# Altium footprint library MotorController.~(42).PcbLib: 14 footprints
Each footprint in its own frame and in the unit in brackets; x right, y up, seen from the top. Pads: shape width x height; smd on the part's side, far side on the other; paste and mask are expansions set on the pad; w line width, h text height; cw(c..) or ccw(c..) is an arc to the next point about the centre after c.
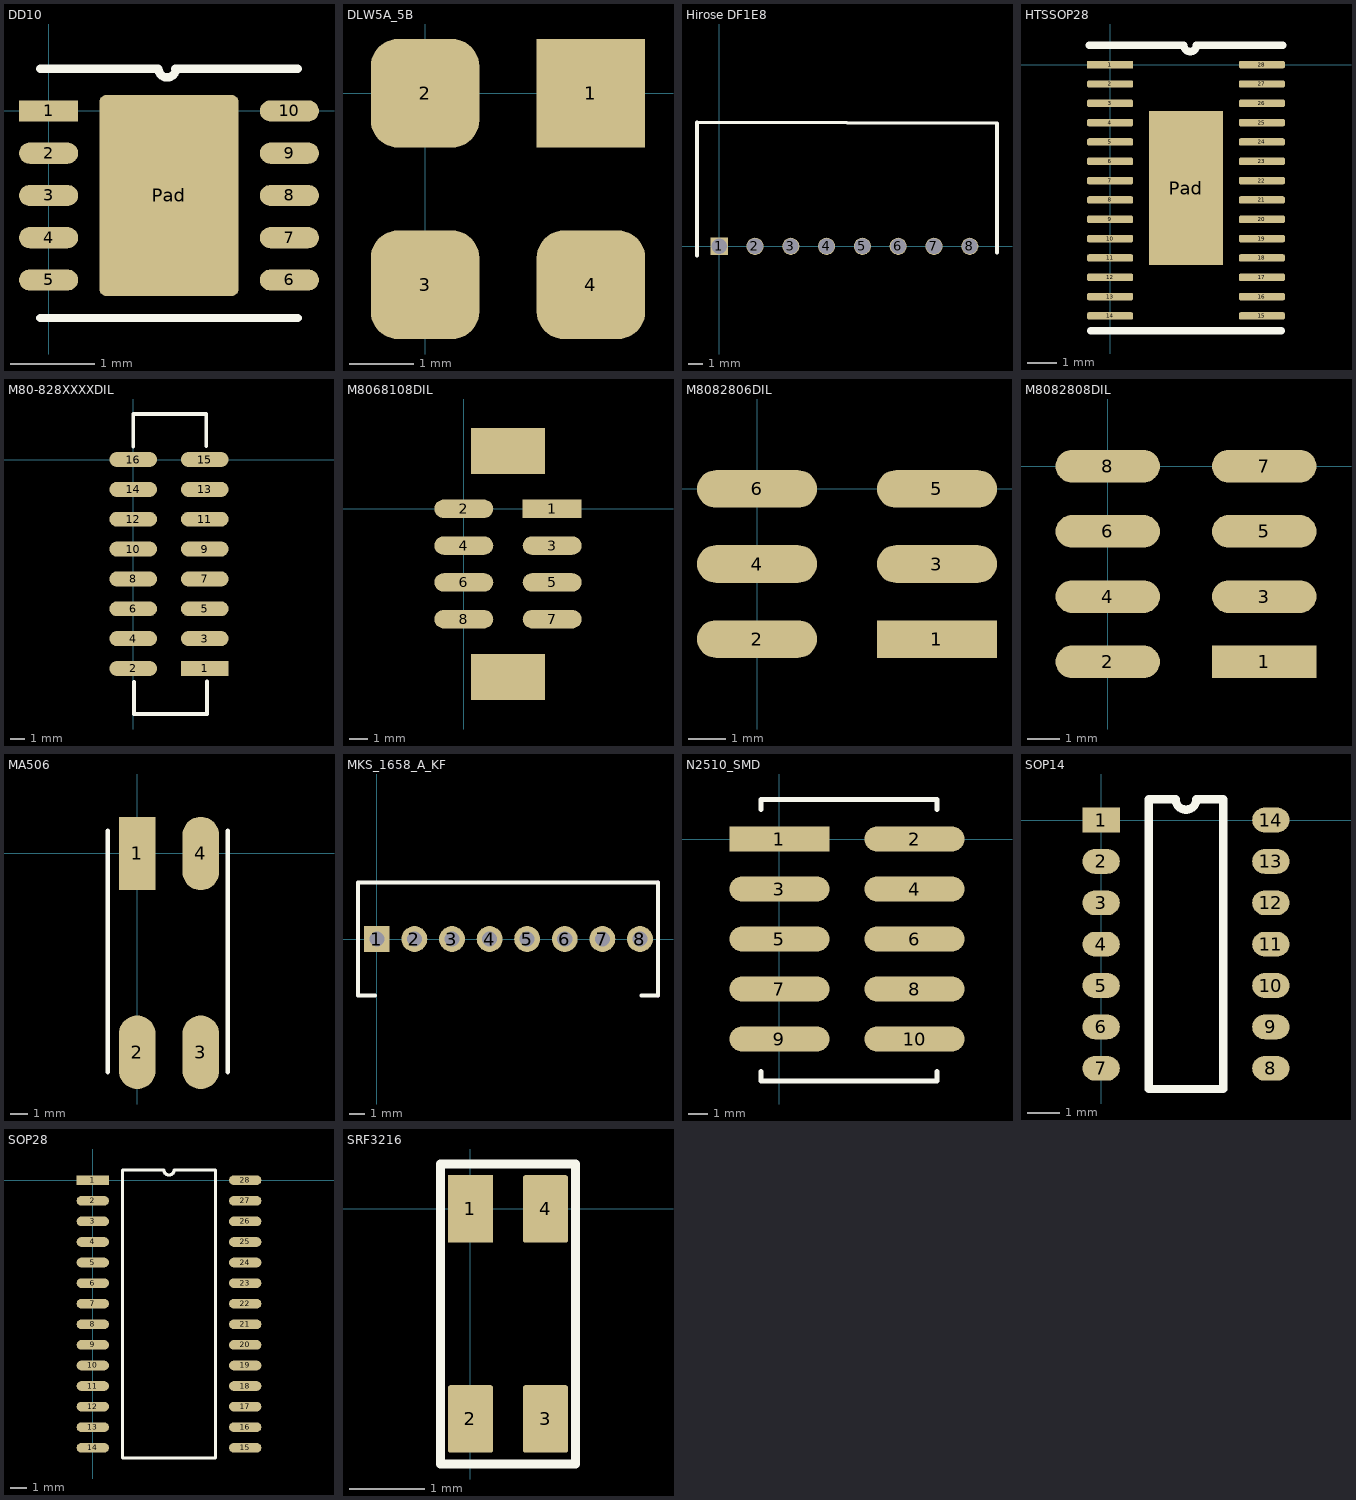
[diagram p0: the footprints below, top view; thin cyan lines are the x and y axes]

## DD10 [mm]
pads (11):
  rect 0.7x0.25 smd: 1(0,0)
  oval 0.7x0.25 smd: 2(0,-0.5) 3(0,-1) 4(0,-1.5) 5(0,-2) 6(2.85,-2) 7(2.85,-1.5) 8(2.85,-1) 9(2.85,-0.5) 10(2.85,0)
  rrect10% 1.65x2.38 smd: Pad(1.425,-1)
Top Overlay:
  lines w0.1: -0.1,-2.45 2.95,-2.45 ; -0.1,0.5 1.3,0.5 ccw(c1.403,0.5) 1.506,0.5 ; 1.5,0.5 2.95,0.5

## DLW5A_5B [mm]
pads (4):
  rect 1.7x1.7 smd: 1(2.6,0)
  rrect50% 1.7x1.7 smd: 2(0,0) 3(0,-3) 4(2.6,-3)

## Hirose DF1E8 [mm] "Hirose DF1E series 8 position"
height 5
pads (8):
  rect 1.2x1.2 hole 1.1: 1(0,0)
  round 1.2 hole 1.1: 2(2.5,0) 3(5,0) 4(7.5,0) 5(10,0) 6(12.5,0) 7(15,0) 8(17.5,0)
Top Overlay:
  lines w0.254: -1.55,-0.65 -1.55,8.65 19.4,8.6 19.4,-0.45

## HTSSOP28 [mm] "HTTSSOP 28 Pin Package, TI"
height 1.2
pads (29):
  rect 1.55x0.25 smd: 1(0,0)
  rrect50% 1.55x0.25 smd: 2(0,-0.65) 3(0,-1.3) 4(0,-1.95) 5(0,-2.6) 6(0,-3.25) 7(0,-3.9) 8(0,-4.55) 9(0,-5.2) 10(0,-5.85) 11(0,-6.5) 12(0,-7.15) 13(0,-7.8) 14(0,-8.45) 15(5.1,-8.45) 16(5.1,-7.8) 17(5.1,-7.15) 18(5.1,-6.5) 19(5.1,-5.85) 20(5.1,-5.2) 21(5.1,-4.55) 22(5.1,-3.9) 23(5.1,-3.25) 24(5.1,-2.6) 25(5.1,-1.95) 26(5.1,-1.3) 27(5.1,-0.65) 28(5.1,0)
  rect 2.5x5.18 smd: Pad(2.55,-4.15)
Top Overlay:
  lines w0.254: -0.7,0.65 2.45,0.65 ; -0.65,-8.95 5.75,-8.95 ; 2.476,0.65 ccw(c2.688,0.65) 2.9,0.65 ; 2.912,0.65 5.8,0.65

## M80-828XXXXDIL [mm]
pads (16):
  rect 3.2x1 smd: 1(4.8,-14)
  oval 3.2x1 smd: 2(0,-14) 3(4.8,-12) 4(0,-12) 5(4.8,-10) 6(0,-10) 7(4.8,-8) 8(0,-8) 9(4.8,-6) 10(0,-6) 11(4.8,-4) 12(0,-4) 13(4.8,-2) 14(0,-2) 15(4.8,0) 16(0,0)
Top Overlay:
  lines w0.254: 0,0.85 0,3.05 4.9,3.05 4.9,0.9 ; 0.05,-14.9 0.05,-17.05 4.95,-17.05 4.95,-14.85
3D body: height 8.96, standoff 0, extent -1.381,-16.95 6.181,2.95

## M8068108DIL [mm]
pads (10):
  rect 3.2x1 smd: 1(4.8,0)
  oval 3.2x1 smd: 2(0,0) 3(4.8,-2) 4(0,-2) 5(4.8,-4) 6(0,-4) 7(4.8,-6) 8(0,-6)
  rect 4x2.5 all layers, no hole: ""(2.4,-9.15) ""(2.4,3.15)

## M8082806DIL [mm] "Harwin 2x3"
pads (6):
  rect 3.2x1 smd: 1(4.8,-4)
  oval 3.2x1 smd: 2(0,-4) 3(4.8,-2) 4(0,-2) 5(4.8,0) 6(0,0)
3D body: height 8.96, standoff 0, extent -1.381,-6.95 6.181,2.95

## M8082808DIL [mm] "Harwin M80-82808 SMT DIL Male Connector"
height 5.2
pads (8):
  rect 3.2x1 smd: 1(4.8,-6)
  oval 3.2x1 smd: 2(0,-6) 3(4.8,-4) 4(0,-4) 5(4.8,-2) 6(0,-2) 7(4.8,0) 8(0,0)

## MA506 [mm]
pads (5):
  rect 2.05x4.1 smd: 1(0,0)
  oval 2.05x4.1 smd: 2(0,-11.1) 3(3.55,-11.1) 4(3.55,0)
  round 0.9 on Top Overlay: ""(-0.2,3.15)
Top Overlay:
  lines w0.254: -1.65,-12.2 -1.65,1.26 ; 5.05,-12.2 5.05,1.26

## MKS_1658_A_KF [mm] "Stocko MKS-1658 Shrouded Header Connector"
height 14
pads (8):
  rect 1.72x1.72 / inner round 1.72 / far side rect 1.72x1.72 hole 1: 1(0,0)
  round 1.72 hole 1: 2(2.5,0) 3(5,0) 4(7.5,0) 5(10,0) 6(12.5,0) 7(15,0) 8(17.5,0)
Top Overlay:
  lines w0.254: -0.1,-3.75 -1.25,-3.75 -1.25,3.75 0.95,3.75 ; 0.9,3.75 2.3,3.75 ; 2.05,3.75 18.7,3.75 18.7,0.85 18.7,-3.75 ; 17.6,-3.75 18.65,-3.75
Mechanical 1:
  lines w0.254: 18.7,-3.75 18.7,3.75

## N2510_SMD [mm]
pads (10):
  rect 5.08x1.27 smd: 1(0,0)
  oval 5.08x1.27 smd: 2(6.86,0) 3(0,-2.54) 4(6.86,-2.54) 5(0,-5.08) 6(6.86,-5.08) 7(0,-7.62) 8(6.86,-7.62) 9(0,-10.16) 10(6.86,-10.16)
Top Overlay:
  lines w0.254: -0.95,-11.8 -0.95,-12.3 8,-12.3 8,-11.8 ; -0.95,1.5 -0.95,2 8,2 8,1.5
3D body: height 10.16, standoff 0, extent -1.804,-15.062 9.372,4.953

## SOP14 [mil]
pads (14):
  rect 45x30 smd: 1(0,0)
  oval 45x30 smd: 2(0,-50) 3(0,-100) 4(0,-150) 5(0,-200) 6(0,-250) 7(0,-300) 8(205,-300) 9(205,-250) 10(205,-200) 11(205,-150) 12(205,-100) 13(205,-50) 14(205,0)
Top Overlay:
  lines w10: 57.5,-325 147.5,-325 147.5,25 115,25 cw(c102.5,25) 90,25 57.5,25 57.5,-325

## SOP28 [mm]
pads (28):
  rect 2x0.6 smd: 1(0,0)
  oval 2x0.6 smd: 2(0,-1.27) 3(0,-2.54) 4(0,-3.81) 5(0,-5.08) 6(0,-6.35) 7(0,-7.62) 8(0,-8.89) 9(0,-10.16) 10(0,-11.43) 11(0,-12.7) 12(0,-13.97) 13(0,-15.24) 14(0,-16.51) 15(9.4,-16.51) 16(9.4,-15.24) 17(9.4,-13.97) 18(9.4,-12.7) 19(9.4,-11.43) 20(9.4,-10.16) 21(9.4,-8.89) 22(9.4,-7.62) 23(9.4,-6.35) 24(9.4,-5.08) 25(9.4,-3.81) 26(9.4,-2.54) 27(9.4,-1.27) 28(9.4,0)
Top Overlay:
  lines w0.2: 1.835,-17.145 7.565,-17.145 7.565,0.635 5.017,0.635 cw(c4.7,0.635) 4.382,0.635 1.835,0.635 1.835,-17.145

## SRF3216 [mm]
pads (4):
  rect 0.6x0.9 smd: 1(0,0)
  rrect10% 0.6x0.9 smd: 2(0,-2.8) 3(1,-2.8) 4(1,0)
Top Overlay:
  lines w0.125: -0.4,-3.4 -0.4,0.6 1.4,0.6 1.4,-3.4 -0.4,-3.4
